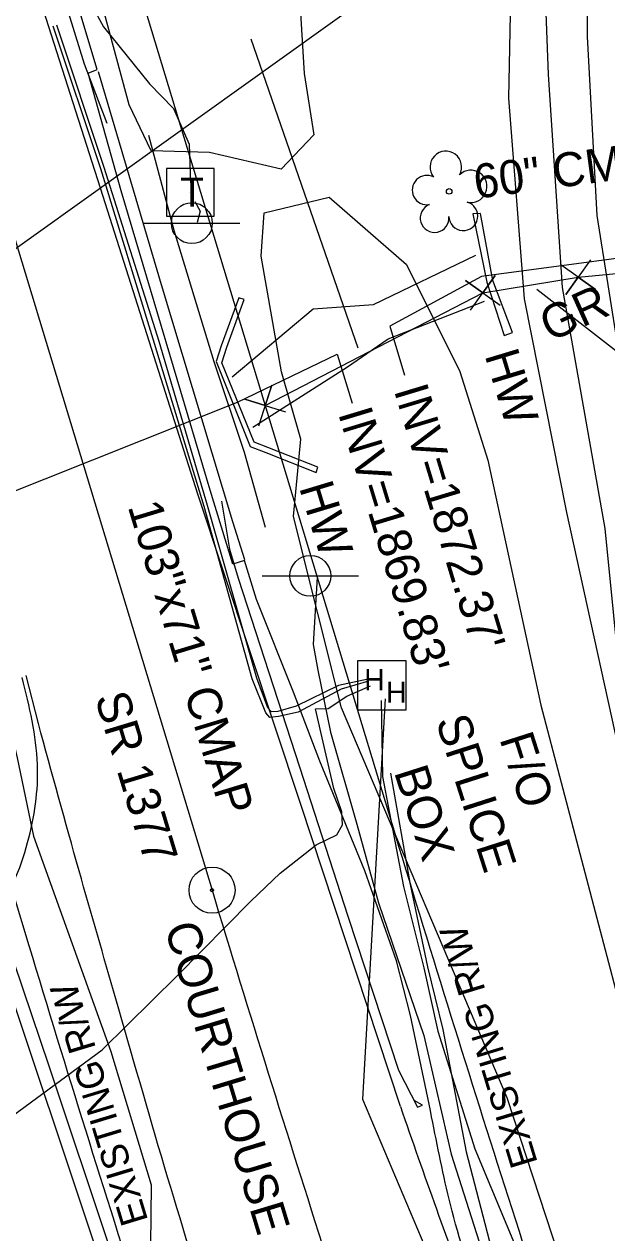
# Model space of a CAD drawing. Extents: x 553786 to 558838, y 502329 to 507342.
# Drawn here: x 555503.7 to 555572.2, y 503924.4 to 504066.5 of the extents above; entities that cross this region are included whole.
import ezdxf

# ---------------------------------------------------------------- set-up
doc = ezdxf.new("R2010")
doc.units = 0
for name, color, linetype in [('Exist Hydro Jurisdictional Stream or Body of Water', 7, 'Continuous'), ('Exist Hydrographic Top of Bank', 7, 'Continuous'), ('Exist Right of Way Line Text', 7, 'Continuous'), ('Exist Roads EOP Text', 7, 'Continuous'), ('Exist Roads Soil Text', 7, 'Continuous'), ('Exist Structure Minor Head and End Wall Text', 7, 'Continuous'), ('Exist Structure Minor Pipes CMAP 103inx71in Invert', 7, 'Continuous'), ('Exist Structure Minor Pipes CMAP 103inx71in Leader', 7, 'Continuous'), ('Exist Structure Minor Pipes CMAP 103inx71in Text', 7, 'Continuous'), ('Exist Structure Minor Pipes CMP 60 Inch', 7, 'Continuous'), ('Exist Structure Minor Pipes CMP 60 Inch Invert', 7, 'Continuous'), ('Exist Structure Minor Pipes CMP 60 Inch Leader', 7, 'Continuous'), ('Exist Structure Minor Pipes CMP 60 Inch Text', 7, 'Continuous'), ('Exist Utilities Sanitary Sewer UG Line', 7, 'Continuous'), ('Exist Utilities Telephone Hand Hole CELL', 7, 'Continuous'), ('Exist Utilities Telephone Hand Hole Text', 7, 'Continuous'), ('Exist Vegetation Hedge Row', 7, 'Continuous'), ('Exist Vegetation Tree CELL', 7, 'Continuous'), ('Exist Vegetation Woods Line', 7, 'Continuous'), ('Exist Vertical Profile Ground Line', 7, 'Continuous'), ('Prop CMT DNC', 7, 'Continuous'), ('Prop Drainage Structure Catch Basin Grate 840 03E Label', 7, 'Continuous'), ('Prop Drainage Structure Headwall CELL', 7, 'Continuous'), ('Prop Drainage Structure Pipe Alternate 24in', 7, 'Continuous'), ('Prop Drainage Structure Pipe Alternate 36in', 7, 'Continuous'), ('Prop Drainage Structure Pipe Plug Label', 7, 'Continuous'), ('Prop Drainage Structure Pipe RCP 15in Class III', 7, 'Continuous'), ('Prop Drainage Structure Pipe RCP 15in Class III Label', 7, 'Continuous'), ('Prop Drainage Structure Pipe RCP 18in Class IV', 7, 'Continuous'), ('Prop Drainage Structure Pipe RCP 48in Class III Label', 7, 'Continuous'), ('Prop Drainage Structure Pipe Removal', 7, 'Continuous'), ('Prop Earthen Structure V Ditch Lateral Detail Label', 7, 'Continuous'), ('Prop Erosion Rip Rap Class B Label', 7, 'Continuous'), ('Prop Erosion Rip Rap Pad at Outlet Label', 7, 'Continuous'), ('Prop Erosion Rip Rap Pad Outlet for Jurisdictional Stream CELL', 7, 'Continuous'), ('Prop Geopak Pavement Shape Independent', 7, 'Continuous'), ('Prop Vertical Profile Grade', 7, 'Continuous'), ('Prop XS SE Text', 7, 'Continuous'), ('Sheet Layout Plan Border', 7, 'Continuous')]:
    doc.layers.add(name, color=color, linetype=linetype)

# ---------------------------------------------------------------- blocks, each defined once
blk = doc.blocks.new('EXIST UTILITIES TELEPHONE PEDESTAL')
at = {"layer": 'Prop Drainage Structure Pipe Removal'}
blk.add_line((0, 0), (0, 0), dxfattribs=at)
blk.add_lwpolyline([(-0.0545, -0.0565), (0.0574, -0.0565), (0.0574, 0.0554), (-0.0545, 0.0554), (-0.0545, -0.0565)], dxfattribs=at)
blk.add_text('T', height=0.0684, dxfattribs=at).set_placement((-0.0226, -0.0343))
blk = doc.blocks.new('EXIST UTILITIES TELEPHONE POLE')
at = {"layer": 'Prop Drainage Structure Pipe RCP 48in Class III Label'}
for p, q in [((-0.1135, 0), (0.11325, 0)), ((0, 0), (0, 0))]:
    blk.add_line(p, q, dxfattribs=at)
blk.add_circle((0, 0), 0.04813, dxfattribs=at)
blk = doc.blocks.new('EXIST SURVEY CENTERLINE POINT')
at = {"layer": 'Prop Drainage Structure Catch Basin Grate 840 03E Label'}
for radius in [0.0542, 0.00375]:
    blk.add_circle((0, 0), radius, dxfattribs=at)

msp = doc.modelspace()

# ---------------------------------------------------------------- linework, layer by layer
at = {"layer": 'Exist Hydro Jurisdictional Stream or Body of Water'}
for points in [[(555528.15, 504025.03), (555537.66, 504033.05), (555544.77, 504033.53), (555556.79, 504039.36)], [(555530.58, 504019.14), (555541.61, 504026.13), (555546.51, 504029.51), (555557.8, 504033.94)]]:
    msp.add_lwpolyline(points, dxfattribs=at)
at = {"layer": 'Exist Hydrographic Top of Bank'}
for points in [[(555544.15, 503989.5), (555540.64, 503988.75), (555535.69, 503986.32), (555533.54, 503985.68), (555532.79, 503985.66), (555532.35, 503986.13), (555531.07, 503989.61), (555525.27, 504009.9), (555519.56, 504029.18), (555513.1, 504049.66), (555507.54, 504066.38)], [(555454.73, 503900.13), (555461.06, 503904.46), (555466.29, 503907.66), (555471.13, 503910.31), (555473.27, 503914.4), (555479.75, 503922.01), (555488.3, 503928.78), (555497.38, 503934.53), (555512.87, 503945.92), (555521.69, 503954.59), (555530.33, 503963.4), (555533.78, 503966.67), (555538.03, 503970.02), (555540.47, 503971.18), (555541.14, 503972.36), (555541.05, 503973.88), (555540.1, 503976.62), (555537.96, 503985.99), (555539.43, 503986.04), (555541.64, 503987.48), (555544.42, 503988.72)], [(555546.14, 503987.16), (555543.47, 503940.11), (555552.96, 503917.69), (555559.34, 503901.27), (555567.72, 503880.79), (555573.74, 503866.88), (555578.16, 503854.22), (555579.5, 503850.08), (555580.11, 503848.77), (555581.48, 503846.16), (555582.1, 503844.29), (555583.96, 503839.09), (555585.42, 503834.09), (555586.7, 503831.85), (555588.11, 503831), (555592.25, 503830.74)], [(555546.78, 503978.43), (555549.06, 503965.33), (555551.1, 503955.67), (555552.92, 503948.29), (555555.67, 503933.93), (555559.33, 503919.76), (555565.36, 503901.7), (555571.99, 503882.34), (555577.36, 503868.05), (555581.03, 503854.9), (555583.9, 503844.8), (555585.49, 503840.07), (555587.73, 503834.98), (555590.12, 503832.07), (555592.04, 503831.34)]]:
    msp.add_lwpolyline(points, dxfattribs=at)
at = {"layer": 'Exist Structure Minor Pipes CMAP 103inx71in Leader'}
msp.add_lwpolyline([(555528.79, 504022.07), (555540.51, 504027.7), (555542.25, 504021.96)], dxfattribs=at)
at = {"layer": 'Exist Structure Minor Pipes CMP 60 Inch'}
msp.add_line((555577.16, 504039.48), (555557.46, 504036.84), dxfattribs=at)
at = {"layer": 'Exist Structure Minor Pipes CMP 60 Inch Leader'}
msp.add_lwpolyline([(555557.46, 504036.84), (555546.7, 504031), (555548.43, 504025.25)], dxfattribs=at)
at = {"layer": 'Exist Utilities Sanitary Sewer UG Line'}
for q in [(555548.76, 504073.12), (555570.8, 503747.32)]:
    msp.add_line((555478.54, 504022.87), q, dxfattribs=at)
at = {"layer": 'Exist Utilities Telephone Hand Hole CELL'}
for p, q in [((555542.9, 503991.63), (555542.9, 503985.9)), ((555548.62, 503991.63), (555542.9, 503991.63)), ((555548.62, 503985.9), (555548.62, 503991.63)), ((555545.76, 503988.77), (555545.76, 503988.77)), ((555542.9, 503985.9), (555548.62, 503985.9))]:
    msp.add_line(p, q, dxfattribs=at)
at = {"layer": 'Exist Vegetation Hedge Row'}
msp.add_lwpolyline([(555546.14, 504097.02), (555535.85, 504073.67), (555536.6, 504060.7), (555537.76, 504053.5), (555533.91, 504049.45), (555525.47, 504051.43), (555518.65, 504051.62), (555516.03, 504057.04), (555505.11, 504097.56)], dxfattribs=at)
at = {"layer": 'Exist Vegetation Tree CELL'}
msp.add_line((555553.66, 504046.84), (555553.66, 504046.84), dxfattribs=at)
msp.add_circle((555553.66, 504046.84), 0.326, dxfattribs=at)
for centre, radius, start, end in [((555553.27, 504049.72), 1.86, 330.1651, 219.7134), ((555551.05, 504047), 1.73, 62.6636, 279.3457), ((555556.21, 504047.43), 1.9, 257.1011, 134.1999), ((555551.95, 504043.72), 1.69, 111.5671, 6.231), ((555555.33, 504043.94), 1.7, 181.2822, 74.56)]:
    msp.add_arc(centre, radius, start, end, dxfattribs=at)
at = {"layer": 'Exist Vegetation Woods Line'}
msp.add_lwpolyline([(555535.38, 504008.6), (555536.24, 504017.71), (555533.95, 504025.61), (555531.57, 504039.21), (555531.91, 504044.34), (555539.54, 504046.16), (555548.64, 504038.23), (555554.9, 504025.67), (555558.19, 504015.26), (555564.45, 503986.44), (555573.99, 503950.07), (555587.78, 503901.83), (555599.94, 503859.2), (555597.38, 503849.85), (555591.55, 503850.13), (555586.43, 503861.1), (555560.49, 503940.27), (555541.01, 503986.11), (555535.38, 504008.6)], dxfattribs=at)
at = {"layer": 'Exist Vertical Profile Ground Line'}
msp.add_lwpolyline([(555433.43, 504150.93), (555435.21, 504143.77), (555439.28, 504132.06), (555443.72, 504117.58), (555448.57, 504102.98), (555451.64, 504099.28), (555458.9, 504092.28), (555463.53, 504086.55), (555466.67, 504083.23), (555473.34, 504070.52), (555475.68, 504065.03), (555477.64, 504058.17), (555484.14, 504035.95), (555490.65, 504015.45), (555495.3, 504004.06), (555498.56, 503994.99), (555500.88, 503989.04), (555502.87, 503980.23), (555504.78, 503971.04), (555509.33, 503958.36), (555513.88, 503945.7), (555518.65, 503930.05), (555518.54, 503922.95)], dxfattribs=at)
at = {"layer": 'Prop CMT DNC'}
for p, q in [((555568.83, 504036.76), (555568.83, 504036.76)), ((555557.62, 504034.91), (555557.62, 504034.91)), ((555532.04, 504021.67), (555532.04, 504021.67))]:
    msp.add_line(p, q, dxfattribs=at)
for points in [[(555570.29, 504038.79), (555567.37, 504034.73), (555568.83, 504036.76), (555570.86, 504035.31), (555566.8, 504038.22)], [(555556.17, 504032.88), (555559.08, 504036.94), (555557.62, 504034.91), (555555.59, 504036.37), (555559.65, 504033.46)], [(555531.28, 504019.28), (555532.8, 504024.05), (555532.04, 504021.67), (555529.66, 504022.42), (555534.42, 504020.91)]]:
    msp.add_lwpolyline(points, dxfattribs=at)
at = {"layer": 'Prop Drainage Structure Headwall CELL'}
msp.add_line((555505.37, 503984.27), (555503.93, 503989.94), dxfattribs=at)
msp.add_lwpolyline([(555547.93, 503939.23), (555536.22, 503974.76), (555524.1, 504011.25), (555512.99, 504046.24), (555501.14, 504083.24), (555490.14, 504118.81), (555482.07, 504143.95)], dxfattribs=at)
msp.add_ellipse((556136.51, 504139.48), major_axis=(244.45, -692.68), ratio=0.846372, start_param=4.702801, end_param=4.737464, dxfattribs=at)
msp.add_spline([(555526.12, 503912.82), (555520.2, 503932.16), (555514.48, 503951.91), (555510.16, 503966.95), (555505.37, 503984.27)], degree=3, dxfattribs=at)
at = {"layer": 'Prop Drainage Structure Pipe Alternate 24in'}
msp.add_lwpolyline([(555425.86, 504224.7), (555428.87, 504213.11), (555437.48, 504180.87), (555443.86, 504161.62), (555449.94, 504139.06), (555455.37, 504118.93), (555462.09, 504098.48), (555472.75, 504066.14), (555481.58, 504035.23), (555486.66, 504014.25), (555493.86, 503987.55), (555500.4, 503962.25), (555506.61, 503944.04), (555513.8, 503922.45), (555526.9, 503890.29), (555537.86, 503859.06), (555549.89, 503821.22), (555549.16, 503799.4), (555550.9, 503782.96), (555554.95, 503765.26), (555558.46, 503752.22), (555561.63, 503739.32), (555563.86, 503731.68)], dxfattribs=at)
at = {"layer": 'Prop Drainage Structure Pipe Alternate 36in'}
msp.add_lwpolyline([(555549.11, 503949.94), (555547.48, 503956.36), (555543.73, 503966.96), (555538.47, 503979.85), (555535.37, 503987.98), (555531, 503998.84), (555529.59, 504003.44), (555528.23, 504003), (555525.56, 504011.7), (555515.09, 504046.92), (555511.24, 504060.74), (555512.29, 504061.19), (555510.85, 504066), (555505.39, 504084.27), (555494.36, 504120.08), (555491.94, 504130), (555488.12, 504136.11), (555484.55, 504141.39)], dxfattribs=at)
for points in [[(555473.8, 503942.81), (555483.53, 503948.42), (555493.32, 503955.02), (555500.1, 503961.5), (555504.11, 503970.27), (555505.27, 503979.46), (555503.47, 503989.67)], [(555561.83, 503902.55), (555557.47, 503915.65), (555553.82, 503927.71), (555551.6, 503938.02), (555549.11, 503949.94)]]:
    msp.add_spline(points, degree=3, dxfattribs=at)
at = {"layer": 'Prop Drainage Structure Pipe Plug Label'}
for p, q in [((555542.97, 504028.41), (555530.39, 504064.74)), ((555563.97, 504035.34), (555587.74, 504016.82))]:
    msp.add_line(p, q, dxfattribs=at)
at = {"layer": 'Prop Drainage Structure Pipe RCP 15in Class III'}
msp.add_line((555481.88, 504003.36), (555528.79, 504022.07), dxfattribs=at)
at = {"layer": 'Prop Drainage Structure Pipe RCP 15in Class III Label'}
for p, q in [((555460.76, 504257.03), (555547.32, 503971.21)), ((555424.8, 504220.5), (555504.25, 503958.16))]:
    msp.add_line(p, q, dxfattribs=at)
for radius in [2842.29, 2887.29]:
    msp.add_arc((558267.58, 504795.09), radius, 196.85, 198.65, dxfattribs=at)
at = {"layer": 'Prop Drainage Structure Pipe RCP 18in Class IV'}
for points in [[(555557.33, 504044.25), (555556.43, 504044.2), (555558.1, 504036.18), (555560.13, 504029.91), (555561.11, 504030.25), (555558.81, 504036.36), (555557.33, 504044.25)], [(555538.01, 504013.78), (555538.24, 504014.4), (555532.33, 504016.75), (555530.73, 504017.37), (555526.93, 504026.7), (555527.54, 504028.51), (555529.58, 504034.12), (555528.95, 504034.32), (555526.87, 504028.7), (555526.28, 504026.84), (555530.27, 504016.84), (555532.11, 504016.16), (555538.01, 504013.78)]]:
    msp.add_lwpolyline(points, dxfattribs=at)
at = {"layer": 'Prop Earthen Structure V Ditch Lateral Detail Label'}
for points in [[(555638.59, 503805.92), (555629.56, 503826.58), (555617.75, 503850.99), (555605.44, 503877.18), (555594.52, 503904.1), (555586.06, 503928.17), (555580.84, 503948.87), (555575.2, 503973.97), (555567.51, 504009.1), (555562.53, 504034.22), (555560.68, 504057.8), (555561.13, 504081.53), (555562.72, 504111.74), (555566.68, 504138.14), (555570.18, 504160.49)], [(555575.33, 504143.83), (555574.71, 504140.81), (555571.85, 504120.36), (555569.88, 504100.7), (555569.77, 504082.91), (555569.88, 504065.05), (555571.01, 504044.01), (555573.6, 504027.71), (555578.83, 504004.96), (555582.52, 503988.23), (555587.14, 503968.6), (555593.42, 503945.47), (555599.18, 503926.11), (555606.22, 503907.94), (555615.2, 503885.88), (555625.44, 503862.63), (555636.69, 503838.87), (555650.14, 503810.94)]]:
    msp.add_lwpolyline(points, dxfattribs=at)
at = {"layer": 'Prop Erosion Rip Rap Class B Label'}
for points in [[(555491.64, 504128.85), (555491.96, 504129.89), (555490.97, 504129.65), (555502.7, 504087.98), (555510.74, 504061.84), (555513.43, 504054.86)], [(555526.88, 504010.41), (555527.82, 504004.78), (555528.86, 504001.38), (555536.06, 503979.18), (555541.74, 503961.61), (555547.71, 503943.52), (555549.94, 503939.16), (555550.51, 503939.41), (555549.56, 503939.95)]]:
    msp.add_lwpolyline(points, dxfattribs=at)
at = {"layer": 'Prop Erosion Rip Rap Pad at Outlet Label'}
for points in [[(555565.32, 504094.29), (555564.57, 504080.26), (555565.3, 504060.58), (555566.93, 504035.53), (555571.98, 504007.2), (555576.03, 503966.29), (555579.7, 503945.61), (555587.95, 503921.14), (555596.42, 503900.01), (555604.58, 503878.81), (555610.35, 503864.5), (555617.45, 503847.74), (555625.46, 503831.68), (555634.15, 503816.36), (555641.9, 503808.58), (555652.28, 503800.81), (555671.17, 503795.1), (555675.77, 503793.35), (555678.04, 503793.15), (555678.52, 503793.55), (555678.23, 503794.12), (555676.61, 503794.11)], [(555509.84, 504072.15), (555511.67, 504068.72), (555513.03, 504066.21), (555518.45, 504059.51), (555521.26, 504056.6), (555523.08, 504052.38), (555523.25, 504047.85)], [(555523.77, 504045.65), (555524.41, 504044.53), (555524.03, 504043.2)], [(555538.16, 504001.49), (555537.67, 503993.56), (555538.24, 503990.56), (555539.73, 503983.25), (555542.8, 503972.44), (555545.34, 503963.2), (555550.68, 503947.61), (555553.88, 503933.65), (555558.35, 503919.63), (555563.87, 503901.2), (555570.28, 503881.72), (555574.88, 503867.51), (555579.43, 503854.5), (555580.72, 503851.11), (555580.88, 503849.34), (555580.66, 503846.35), (555581.08, 503843.83), (555582.58, 503838.12), (555583.84, 503831.22), (555585.88, 503827.99)]]:
    msp.add_lwpolyline(points, dxfattribs=at)
at = {"layer": 'Prop Erosion Rip Rap Pad Outlet for Jurisdictional Stream CELL'}
for points in [[(555529.63, 504003.53), (555528.22, 504007.98), (555519.86, 504035.84), (555512.45, 504060.9)], [(555518.32, 504053.46), (555521.29, 504042.29), (555526, 504026.86), (555529.57, 504016.18), (555532.03, 504007.37)]]:
    msp.add_lwpolyline(points, dxfattribs=at)
at = {"layer": 'Prop Vertical Profile Grade'}
for points in [[(555544.18, 503989.24), (555540.96, 503988.3), (555535.91, 503985.63), (555533.58, 503985.12), (555532.59, 503985), (555532.12, 503985.52), (555530.52, 503989.53), (555524.88, 504009.79), (555519.02, 504028.96), (555512.71, 504049.48), (555507.1, 504066.27)], [(555545.68, 503986.99), (555545.84, 503978.03), (555548.29, 503965.12), (555550.67, 503955.56), (555552.34, 503948.1), (555556.68, 503934.25), (555562.34, 503920.73), (555568.8, 503903.21), (555575.76, 503883.5), (555579.66, 503868.5), (555582.43, 503855.45), (555584.56, 503845.1), (555586.11, 503840.52), (555588.25, 503835.4), (555590.52, 503832.61), (555592.08, 503831.76)]]:
    msp.add_lwpolyline(points, dxfattribs=at)
at = {"layer": 'Prop XS SE Text'}
for p, q in [((555568.83, 504036.76), (555577.42, 504037.57)), ((555557.62, 504034.91), (555568.83, 504036.76)), ((555532.04, 504021.67), (555557.62, 504034.91))]:
    msp.add_line(p, q, dxfattribs=at)
at = {"layer": 'Sheet Layout Plan Border'}
msp.add_line((555446.33, 504227.02), (555525.79, 503964.68), dxfattribs=at)
msp.add_arc((558267.58, 504795.09), 2864.79, 196.85, 198.65, dxfattribs=at)

# ---------------------------------------------------------------- block references
at = {"layer": 'Prop Drainage Structure Pipe RCP 48in Class III Label', "xscale": 50, "yscale": 50}
for p in [(555523.41, 504043.11), (555537.34, 504001.64)]:
    msp.add_blockref('EXIST UTILITIES TELEPHONE POLE', p, dxfattribs=at)
at = {"layer": 'Prop Drainage Structure Pipe Removal', "xscale": 50, "yscale": 50}
msp.add_blockref('EXIST UTILITIES TELEPHONE PEDESTAL', (555523.17, 504046.76), dxfattribs=at)
at = {"layer": 'Prop Geopak Pavement Shape Independent', "xscale": 50, "yscale": 50}
msp.add_blockref('EXIST SURVEY CENTERLINE POINT', (555525.79, 503964.68), dxfattribs=at)

# ---------------------------------------------------------------- texts
at = {"layer": 'Exist Right of Way Line Text'}
for p in [(555564.09, 503932.64), (555518.3, 503925.84)]:
    msp.add_text('EXISTING R/W', height=3.2, rotation=106.85, dxfattribs=at).set_placement(p)
at = {"layer": 'Exist Roads EOP Text'}
msp.add_text('SR 1377     COURTHOUSE DR.', height=4, rotation=286.85, dxfattribs=at).set_placement((555511.98, 503987.34))
at = {"layer": 'Exist Roads Soil Text'}
msp.add_text('GR', height=4, rotation=24.3449, dxfattribs=at).set_placement((555565.5, 504029.1))
at = {"layer": 'Exist Structure Minor Head and End Wall Text'}
for p in [(555557.81, 504027.59), (555536, 504012.05)]:
    msp.add_text('HW', height=4, rotation=286.85, dxfattribs=at).set_placement(p)
at = {"layer": 'Exist Structure Minor Pipes CMAP 103inx71in Invert'}
msp.add_text("INV=1869.83'", height=4, rotation=286.85, dxfattribs=at).set_placement((555540.58, 504020.76))
at = {"layer": 'Exist Structure Minor Pipes CMAP 103inx71in Text'}
msp.add_text('103"x71" CMAP', height=4, rotation=286.85, dxfattribs=at).set_placement((555515.85, 504009.81))
at = {"layer": 'Exist Structure Minor Pipes CMP 60 Inch Invert'}
msp.add_text("INV=1872.37'", height=4, rotation=286.85, dxfattribs=at).set_placement((555547.14, 504023.48))
at = {"layer": 'Exist Structure Minor Pipes CMP 60 Inch Text'}
msp.add_text('60" CMP', height=4, rotation=7.6215, dxfattribs=at).set_placement((555556.82, 504045.97))
at = {"layer": 'Exist Utilities Telephone Hand Hole CELL'}
for p in [(555543.67, 503988.17), (555546.25, 503986.71)]:
    msp.add_text('H', height=2.5, dxfattribs=at).set_placement(p)
at = {"layer": 'Exist Utilities Telephone Hand Hole Text'}
for s, p in [('SPLICE', (555552.05, 503984.61)), ('F/O', (555559.55, 503982.49)), ('BOX', (555547.15, 503978.59))]:
    msp.add_text(s, height=4, rotation=287.75, dxfattribs=at).set_placement(p)

doc.saveas('drawing.dxf')
